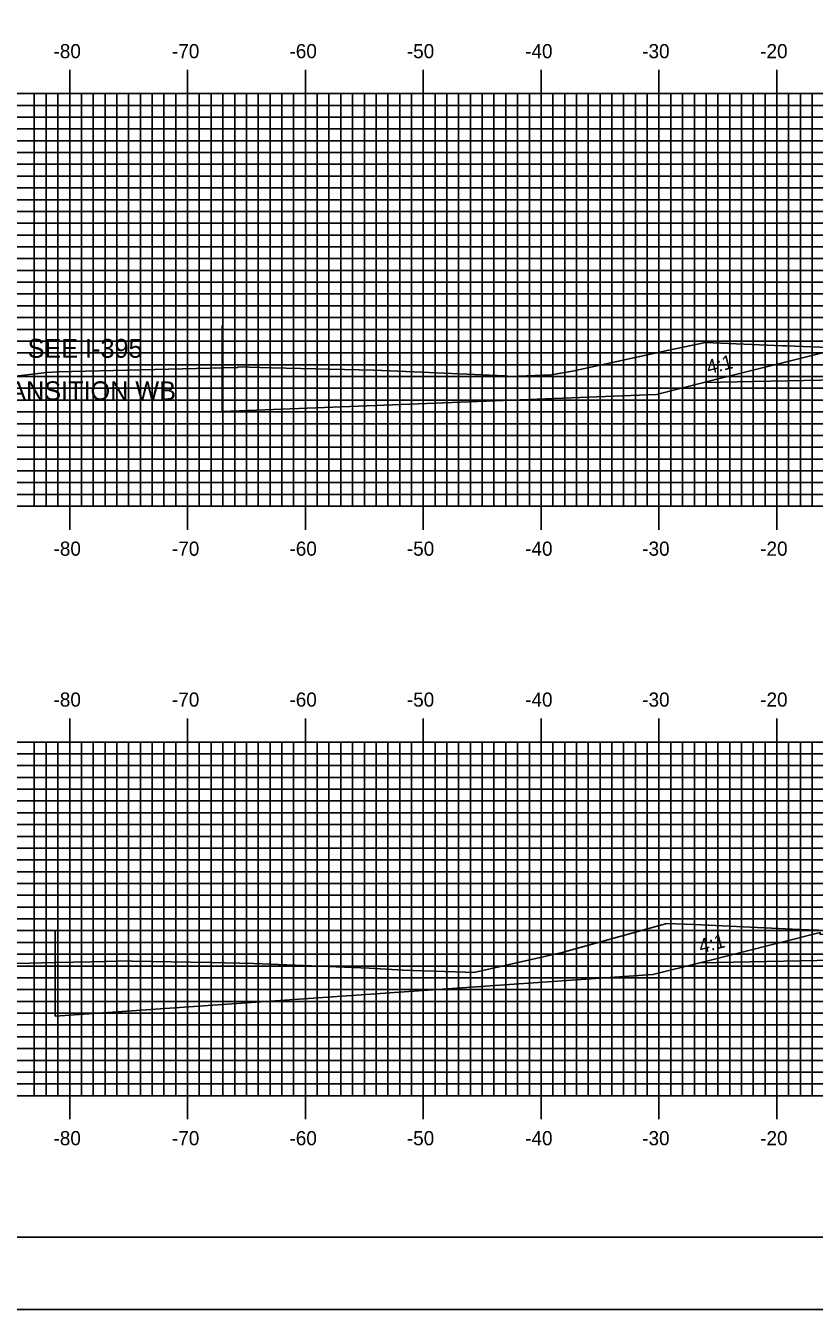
# Model space of a CAD drawing. Extents: x 852934 to 853277, y 364661 to 364881.
# Drawn here: x 853016 to 853083, y 364661.3 to 364770.1 of the extents above; entities that cross this region are included whole.
import ezdxf

# ---------------------------------------------------------------- set-up
doc = ezdxf.new("R2010")
doc.units = 0
for name, color, linetype in [('ANNOTATION', 7, 'Continuous'), ('BORDER', 7, 'Continuous'), ('D_Roadway_SlopeLines', 7, 'Continuous'), ('D_Roadway_SubGrade', 7, 'Continuous'), ('H_V ANNOTATION', 7, 'Continuous'), ('M_Roadway_Centerline', 7, 'Continuous'), ('MAJOR', 7, 'Continuous'), ('MINOR', 7, 'Continuous'), ('PLOT BOUNDARY', 7, 'Continuous'), ('S_Roadway_Centerline', 7, 'Continuous')]:
    doc.layers.add(name, color=color, linetype=linetype)

msp = doc.modelspace()

# ---------------------------------------------------------------- linework, layer by layer
at = {"layer": 'ANNOTATION'}
msp.add_lwpolyline([(853073.58, 364739.85), (853069.58, 364738.85), (853032.72, 364737.41)], dxfattribs=at)
at = {"layer": 'BORDER'}
msp.add_lwpolyline([(852950.18, 364667.37), (853270.18, 364667.37), (853270.18, 364877.37), (852950.18, 364877.37)], close=True, dxfattribs=at)
at = {"layer": 'D_Roadway_SlopeLines'}
msp.add_lwpolyline([(853073.26, 364690.65), (853069.26, 364689.65), (853018.54, 364686.13)], dxfattribs=at)
at = {"layer": 'D_Roadway_SubGrade'}
for p, q in [((853032.72, 364744.7), (853032.72, 364737.41)), ((853018.54, 364693.42), (853018.54, 364686.13))]:
    msp.add_line(p, q, dxfattribs=at)
for points in [[(853087.78, 364740.14), (853073.57, 364739.85), (853083.78, 364742.4), (853083.78, 364742.24), (853087.78, 364742.3), (853087.78, 364742.14)], [(853087.47, 364690.93), (853073.26, 364690.65), (853083.47, 364693.2), (853083.47, 364693.03), (853087.47, 364693.1), (853087.47, 364692.93)]]:
    msp.add_lwpolyline(points, close=True, dxfattribs=at)
at = {"layer": 'MAJOR'}
for p, q in [((853019.78, 364766.37), (853019.78, 364764.37)), ((853029.78, 364766.37), (853029.78, 364764.37)), ((853039.78, 364766.37), (853039.78, 364764.37)), ((853049.78, 364766.37), (853049.78, 364764.37)), ((853059.78, 364766.37), (853059.78, 364764.37)), ((853069.78, 364766.37), (853069.78, 364764.37)), ((853079.78, 364766.37), (853079.78, 364764.37)), ((852959.78, 364764.37), (853239.78, 364764.37)), ((852959.78, 364764.37), (853239.78, 364764.37)), ((853019.78, 364729.37), (853019.78, 364764.37)), ((853029.78, 364729.37), (853029.78, 364764.37)), ((853039.78, 364729.37), (853039.78, 364764.37)), ((853049.78, 364729.37), (853049.78, 364764.37)), ((853059.78, 364729.37), (853059.78, 364764.37)), ((853069.78, 364729.37), (853069.78, 364764.37)), ((853079.78, 364729.37), (853079.78, 364764.37)), ((852959.78, 364759.37), (853239.78, 364759.37)), ((852959.78, 364754.37), (853239.78, 364754.37)), ((852959.78, 364749.37), (853239.78, 364749.37)), ((852959.78, 364744.37), (853239.78, 364744.37)), ((852959.78, 364739.37), (853239.78, 364739.37)), ((852959.78, 364734.37), (853239.78, 364734.37)), ((852959.78, 364729.37), (853239.78, 364729.37)), ((852959.78, 364729.37), (853239.78, 364729.37)), ((853019.78, 364727.37), (853019.78, 364729.37)), ((853029.78, 364727.37), (853029.78, 364729.37)), ((853039.78, 364727.37), (853039.78, 364729.37)), ((853049.78, 364727.37), (853049.78, 364729.37)), ((853059.78, 364727.37), (853059.78, 364729.37)), ((853069.78, 364727.37), (853069.78, 364729.37)), ((853079.78, 364727.37), (853079.78, 364729.37)), ((853019.78, 364711.37), (853019.78, 364709.37)), ((853029.78, 364711.37), (853029.78, 364709.37)), ((853039.78, 364711.37), (853039.78, 364709.37)), ((853049.78, 364711.37), (853049.78, 364709.37)), ((853059.78, 364711.37), (853059.78, 364709.37)), ((853069.78, 364711.37), (853069.78, 364709.37)), ((853079.78, 364711.37), (853079.78, 364709.37)), ((852959.78, 364709.37), (853239.78, 364709.37)), ((852959.78, 364709.37), (853239.78, 364709.37)), ((853019.78, 364679.37), (853019.78, 364709.37)), ((853029.78, 364679.37), (853029.78, 364709.37)), ((853039.78, 364679.37), (853039.78, 364709.37)), ((853049.78, 364679.37), (853049.78, 364709.37)), ((853059.78, 364679.37), (853059.78, 364709.37)), ((853069.78, 364679.37), (853069.78, 364709.37)), ((853079.78, 364679.37), (853079.78, 364709.37)), ((852959.78, 364704.37), (853239.78, 364704.37)), ((852959.78, 364699.37), (853239.78, 364699.37)), ((852959.78, 364694.37), (853239.78, 364694.37)), ((852959.78, 364689.37), (853239.78, 364689.37)), ((852959.78, 364684.37), (853239.78, 364684.37)), ((852959.78, 364679.37), (853239.78, 364679.37)), ((852959.78, 364679.37), (853239.78, 364679.37)), ((853019.78, 364677.37), (853019.78, 364679.37)), ((853029.78, 364677.37), (853029.78, 364679.37)), ((853039.78, 364677.37), (853039.78, 364679.37)), ((853049.78, 364677.37), (853049.78, 364679.37)), ((853059.78, 364677.37), (853059.78, 364679.37)), ((853069.78, 364677.37), (853069.78, 364679.37)), ((853079.78, 364677.37), (853079.78, 364679.37))]:
    msp.add_line(p, q, dxfattribs=at)
at = {"layer": 'MINOR'}
for p, q in [((853016.78, 364729.37), (853016.78, 364764.37)), ((853017.78, 364729.37), (853017.78, 364764.37)), ((853018.78, 364729.37), (853018.78, 364764.37)), ((853020.78, 364729.37), (853020.78, 364764.37)), ((853021.78, 364729.37), (853021.78, 364764.37)), ((853022.78, 364729.37), (853022.78, 364764.37)), ((853023.78, 364729.37), (853023.78, 364764.37)), ((853024.78, 364729.37), (853024.78, 364764.37)), ((853025.78, 364729.37), (853025.78, 364764.37)), ((853026.78, 364729.37), (853026.78, 364764.37)), ((853027.78, 364729.37), (853027.78, 364764.37)), ((853028.78, 364729.37), (853028.78, 364764.37)), ((853030.78, 364729.37), (853030.78, 364764.37)), ((853031.78, 364729.37), (853031.78, 364764.37)), ((853032.78, 364729.37), (853032.78, 364764.37)), ((853033.78, 364729.37), (853033.78, 364764.37)), ((853034.78, 364729.37), (853034.78, 364764.37)), ((853035.78, 364729.37), (853035.78, 364764.37)), ((853036.78, 364729.37), (853036.78, 364764.37)), ((853037.78, 364729.37), (853037.78, 364764.37)), ((853038.78, 364729.37), (853038.78, 364764.37)), ((853040.78, 364729.37), (853040.78, 364764.37)), ((853041.78, 364729.37), (853041.78, 364764.37)), ((853042.78, 364729.37), (853042.78, 364764.37)), ((853043.78, 364729.37), (853043.78, 364764.37)), ((853044.78, 364729.37), (853044.78, 364764.37)), ((853045.78, 364729.37), (853045.78, 364764.37)), ((853046.78, 364729.37), (853046.78, 364764.37)), ((853047.78, 364729.37), (853047.78, 364764.37)), ((853048.78, 364729.37), (853048.78, 364764.37)), ((853050.78, 364729.37), (853050.78, 364764.37)), ((853051.78, 364729.37), (853051.78, 364764.37)), ((853052.78, 364729.37), (853052.78, 364764.37)), ((853053.78, 364729.37), (853053.78, 364764.37)), ((853054.78, 364729.37), (853054.78, 364764.37)), ((853055.78, 364729.37), (853055.78, 364764.37)), ((853056.78, 364729.37), (853056.78, 364764.37)), ((853057.78, 364729.37), (853057.78, 364764.37)), ((853058.78, 364729.37), (853058.78, 364764.37)), ((853060.78, 364729.37), (853060.78, 364764.37)), ((853061.78, 364729.37), (853061.78, 364764.37)), ((853062.78, 364729.37), (853062.78, 364764.37)), ((853063.78, 364729.37), (853063.78, 364764.37)), ((853064.78, 364729.37), (853064.78, 364764.37)), ((853065.78, 364729.37), (853065.78, 364764.37)), ((853066.78, 364729.37), (853066.78, 364764.37)), ((853067.78, 364729.37), (853067.78, 364764.37)), ((853068.78, 364729.37), (853068.78, 364764.37)), ((853070.78, 364729.37), (853070.78, 364764.37)), ((853071.78, 364729.37), (853071.78, 364764.37)), ((853072.78, 364729.37), (853072.78, 364764.37)), ((853073.78, 364729.37), (853073.78, 364764.37)), ((853074.78, 364729.37), (853074.78, 364764.37)), ((853075.78, 364729.37), (853075.78, 364764.37)), ((853076.78, 364729.37), (853076.78, 364764.37)), ((853077.78, 364729.37), (853077.78, 364764.37)), ((853078.78, 364729.37), (853078.78, 364764.37)), ((853080.78, 364729.37), (853080.78, 364764.37)), ((853081.78, 364729.37), (853081.78, 364764.37)), ((853082.78, 364729.37), (853082.78, 364764.37)), ((852959.78, 364763.37), (853239.78, 364763.37)), ((852959.78, 364762.37), (853239.78, 364762.37)), ((852959.78, 364761.37), (853239.78, 364761.37)), ((852959.78, 364760.37), (853239.78, 364760.37)), ((852959.78, 364758.37), (853239.78, 364758.37)), ((852959.78, 364757.37), (853239.78, 364757.37)), ((852959.78, 364756.37), (853239.78, 364756.37)), ((852959.78, 364755.37), (853239.78, 364755.37)), ((852959.78, 364753.37), (853239.78, 364753.37)), ((852959.78, 364752.37), (853239.78, 364752.37)), ((852959.78, 364751.37), (853239.78, 364751.37)), ((852959.78, 364750.37), (853239.78, 364750.37)), ((852959.78, 364748.37), (853239.78, 364748.37)), ((852959.78, 364747.37), (853239.78, 364747.37)), ((852959.78, 364746.37), (853239.78, 364746.37)), ((852959.78, 364745.37), (853239.78, 364745.37)), ((852959.78, 364743.37), (853239.78, 364743.37)), ((852959.78, 364742.37), (853239.78, 364742.37)), ((852959.78, 364741.37), (853239.78, 364741.37)), ((852959.78, 364740.37), (853239.78, 364740.37)), ((852959.78, 364738.37), (853239.78, 364738.37)), ((852959.78, 364737.37), (853239.78, 364737.37)), ((852959.78, 364736.37), (853239.78, 364736.37)), ((852959.78, 364735.37), (853239.78, 364735.37)), ((852959.78, 364733.37), (853239.78, 364733.37)), ((852959.78, 364732.37), (853239.78, 364732.37)), ((852959.78, 364731.37), (853239.78, 364731.37)), ((852959.78, 364730.37), (853239.78, 364730.37)), ((853016.78, 364679.37), (853016.78, 364709.37)), ((853017.78, 364679.37), (853017.78, 364709.37)), ((853018.78, 364679.37), (853018.78, 364709.37)), ((853020.78, 364679.37), (853020.78, 364709.37)), ((853021.78, 364679.37), (853021.78, 364709.37)), ((853022.78, 364679.37), (853022.78, 364709.37)), ((853023.78, 364679.37), (853023.78, 364709.37)), ((853024.78, 364679.37), (853024.78, 364709.37)), ((853025.78, 364679.37), (853025.78, 364709.37)), ((853026.78, 364679.37), (853026.78, 364709.37)), ((853027.78, 364679.37), (853027.78, 364709.37)), ((853028.78, 364679.37), (853028.78, 364709.37)), ((853030.78, 364679.37), (853030.78, 364709.37)), ((853031.78, 364679.37), (853031.78, 364709.37)), ((853032.78, 364679.37), (853032.78, 364709.37)), ((853033.78, 364679.37), (853033.78, 364709.37)), ((853034.78, 364679.37), (853034.78, 364709.37)), ((853035.78, 364679.37), (853035.78, 364709.37)), ((853036.78, 364679.37), (853036.78, 364709.37)), ((853037.78, 364679.37), (853037.78, 364709.37)), ((853038.78, 364679.37), (853038.78, 364709.37)), ((853040.78, 364679.37), (853040.78, 364709.37)), ((853041.78, 364679.37), (853041.78, 364709.37)), ((853042.78, 364679.37), (853042.78, 364709.37)), ((853043.78, 364679.37), (853043.78, 364709.37)), ((853044.78, 364679.37), (853044.78, 364709.37)), ((853045.78, 364679.37), (853045.78, 364709.37)), ((853046.78, 364679.37), (853046.78, 364709.37)), ((853047.78, 364679.37), (853047.78, 364709.37)), ((853048.78, 364679.37), (853048.78, 364709.37)), ((853050.78, 364679.37), (853050.78, 364709.37)), ((853051.78, 364679.37), (853051.78, 364709.37)), ((853052.78, 364679.37), (853052.78, 364709.37)), ((853053.78, 364679.37), (853053.78, 364709.37)), ((853054.78, 364679.37), (853054.78, 364709.37)), ((853055.78, 364679.37), (853055.78, 364709.37)), ((853056.78, 364679.37), (853056.78, 364709.37)), ((853057.78, 364679.37), (853057.78, 364709.37)), ((853058.78, 364679.37), (853058.78, 364709.37)), ((853060.78, 364679.37), (853060.78, 364709.37)), ((853061.78, 364679.37), (853061.78, 364709.37)), ((853062.78, 364679.37), (853062.78, 364709.37)), ((853063.78, 364679.37), (853063.78, 364709.37)), ((853064.78, 364679.37), (853064.78, 364709.37)), ((853065.78, 364679.37), (853065.78, 364709.37)), ((853066.78, 364679.37), (853066.78, 364709.37)), ((853067.78, 364679.37), (853067.78, 364709.37)), ((853068.78, 364679.37), (853068.78, 364709.37)), ((853070.78, 364679.37), (853070.78, 364709.37)), ((853071.78, 364679.37), (853071.78, 364709.37)), ((853072.78, 364679.37), (853072.78, 364709.37)), ((853073.78, 364679.37), (853073.78, 364709.37)), ((853074.78, 364679.37), (853074.78, 364709.37)), ((853075.78, 364679.37), (853075.78, 364709.37)), ((853076.78, 364679.37), (853076.78, 364709.37)), ((853077.78, 364679.37), (853077.78, 364709.37)), ((853078.78, 364679.37), (853078.78, 364709.37)), ((853080.78, 364679.37), (853080.78, 364709.37)), ((853081.78, 364679.37), (853081.78, 364709.37)), ((853082.78, 364679.37), (853082.78, 364709.37)), ((852959.78, 364708.37), (853239.78, 364708.37)), ((852959.78, 364707.37), (853239.78, 364707.37)), ((852959.78, 364706.37), (853239.78, 364706.37)), ((852959.78, 364705.37), (853239.78, 364705.37)), ((852959.78, 364703.37), (853239.78, 364703.37)), ((852959.78, 364702.37), (853239.78, 364702.37)), ((852959.78, 364701.37), (853239.78, 364701.37)), ((852959.78, 364700.37), (853239.78, 364700.37)), ((852959.78, 364698.37), (853239.78, 364698.37)), ((852959.78, 364697.37), (853239.78, 364697.37)), ((852959.78, 364696.37), (853239.78, 364696.37)), ((852959.78, 364695.37), (853239.78, 364695.37)), ((852959.78, 364693.37), (853239.78, 364693.37)), ((852959.78, 364692.37), (853239.78, 364692.37)), ((852959.78, 364691.37), (853239.78, 364691.37)), ((852959.78, 364690.37), (853239.78, 364690.37)), ((852959.78, 364688.37), (853239.78, 364688.37)), ((852959.78, 364687.37), (853239.78, 364687.37)), ((852959.78, 364686.37), (853239.78, 364686.37)), ((852959.78, 364685.37), (853239.78, 364685.37)), ((852959.78, 364683.37), (853239.78, 364683.37)), ((852959.78, 364682.37), (853239.78, 364682.37)), ((852959.78, 364681.37), (853239.78, 364681.37)), ((852959.78, 364680.37), (853239.78, 364680.37))]:
    msp.add_line(p, q, dxfattribs=at)
at = {"layer": 'PLOT BOUNDARY'}
msp.add_lwpolyline([(852933.99, 364661.25), (853273.99, 364661.25), (853273.99, 364881.25), (852933.99, 364881.25)], close=True, dxfattribs=at)
at = {"layer": 'S_Roadway_Centerline'}
for points in [[(853014.93, 364740.36), (853017.85, 364740.71), (853018.8, 364740.78), (853032.86, 364741.1), (853034.05, 364741.14), (853034.06, 364741.19), (853036.89, 364741.12), (853045.6, 364740.91), (853048.98, 364740.76), (853056.69, 364740.43), (853057.15, 364740.37), (853060.64, 364740.52), (853062.45, 364740.82), (853070.61, 364742.6), (853073.72, 364743.27), (853080.27, 364742.98), (853080.57, 364742.96), (853085.62, 364742.77)], [(853011.98, 364690.51), (853018.57, 364690.67), (853021.57, 364690.72), (853024.88, 364690.82), (853025.07, 364690.78), (853031.73, 364690.66), (853035.4, 364690.59), (853045.19, 364690.18), (853047.6, 364690.06), (853048.05, 364690.01), (853053.36, 364689.84), (853053.88, 364689.83), (853054.22, 364689.86), (853061.56, 364691.53), (853070.34, 364693.95), (853070.36, 364693.99), (853072.8, 364693.88), (853081.71, 364693.46), (853083.32, 364693.41)]]:
    msp.add_lwpolyline(points, dxfattribs=at)

# ---------------------------------------------------------------- texts
at = {"layer": 'ANNOTATION'}
for s, p in [('SEE I-395 ', (853016.21, 364741.96)), ('TRANSITION WB', (853011.8, 364738.36))]:
    msp.add_text(s, height=1.6, dxfattribs=at).set_placement(p)
for p in [(853073.98, 364740.55), (853073.32, 364691.44)]:
    msp.add_text('4:1', height=1.2, rotation=14.0362, dxfattribs=at).set_placement(p)
at = {"layer": 'H_V ANNOTATION'}
for s, p in [('-80', (853018.41, 364767.37)), ('-70', (853028.46, 364767.37)), ('-60', (853038.43, 364767.37)), ('-50', (853048.39, 364767.37)), ('-40', (853058.43, 364767.37)), ('-30', (853068.36, 364767.37)), ('-20', (853078.37, 364767.37)), ('-80', (853018.41, 364725.17)), ('-70', (853028.46, 364725.17)), ('-60', (853038.43, 364725.17)), ('-50', (853048.39, 364725.17)), ('-40', (853058.43, 364725.17)), ('-30', (853068.36, 364725.17)), ('-20', (853078.37, 364725.17)), ('-80', (853018.41, 364712.37)), ('-70', (853028.46, 364712.37)), ('-60', (853038.43, 364712.37)), ('-50', (853048.39, 364712.37)), ('-40', (853058.43, 364712.37)), ('-30', (853068.36, 364712.37)), ('-20', (853078.37, 364712.37)), ('-80', (853018.41, 364675.17)), ('-70', (853028.46, 364675.17)), ('-60', (853038.43, 364675.17)), ('-50', (853048.39, 364675.17)), ('-40', (853058.43, 364675.17)), ('-30', (853068.36, 364675.17)), ('-20', (853078.37, 364675.17))]:
    msp.add_text(s, height=1.2, dxfattribs=at).set_placement(p)
at = {"layer": 'M_Roadway_Centerline'}
for s, p in [('C', (853034.05, 364741.19)), ('L', (853034.06, 364741.18)), ('C', (853024.87, 364690.82)), ('L', (853024.88, 364690.81))]:
    msp.add_text(s, height=0.0146, dxfattribs=at).set_placement(p)

doc.saveas('drawing.dxf')
